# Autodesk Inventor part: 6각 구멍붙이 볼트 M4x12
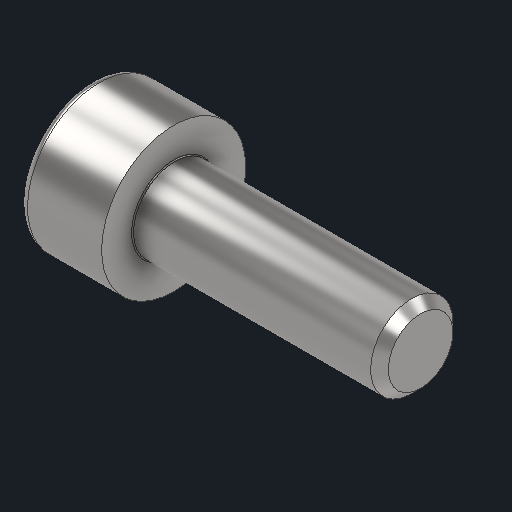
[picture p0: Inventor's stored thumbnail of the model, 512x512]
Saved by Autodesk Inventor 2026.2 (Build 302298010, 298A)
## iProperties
Created: 2026-04
Part Number: 6각 구멍붙이 볼트 M4x12
Material: 강철, 연강
Description: 6각머리 태핑 나사
Document SubType Name: Modeling
Designer: PC2-02
Density: 7.85 g/cm^3
Appearance: 기본값
Author: jhkim
Sending System: Autodesk Inventor 2027
Preprocessor: ST-DEVELOPER v20.1
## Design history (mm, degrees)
feature "Solid1"
node "솔리드1"
